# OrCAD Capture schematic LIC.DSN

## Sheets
1 Jogo Roleta Serie: size A; title: Jogo da Roleta Serie
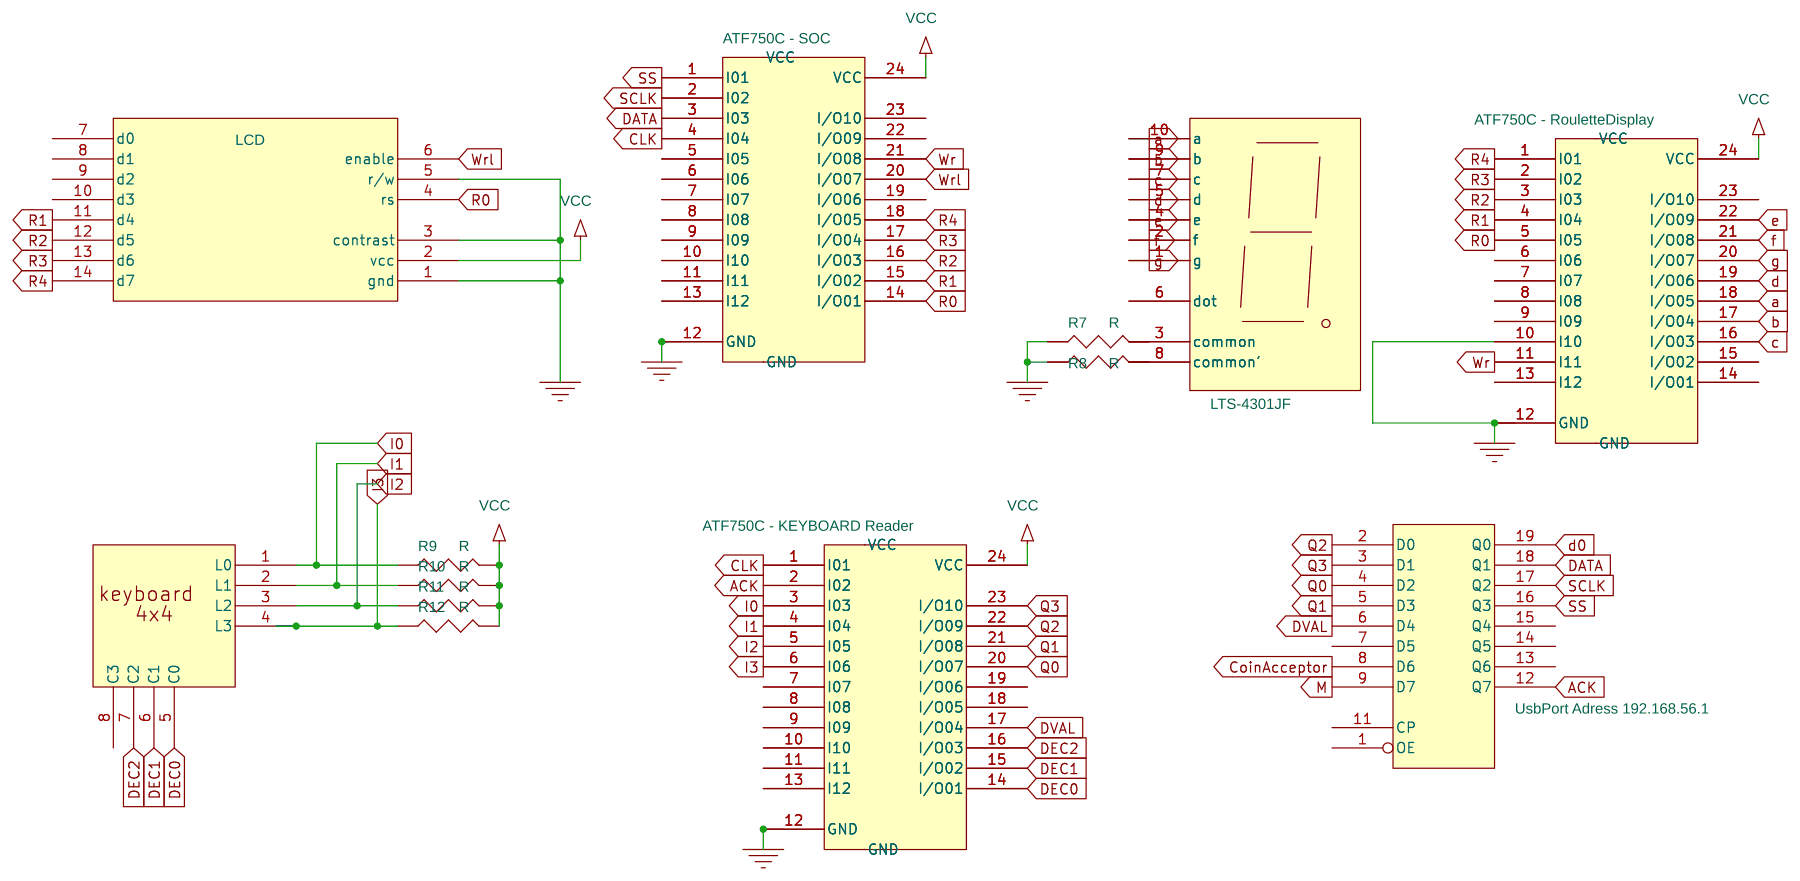
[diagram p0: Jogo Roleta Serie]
2 Jogo Roleta Paralelo: size A; title: Jogo da Roleta Paralelo
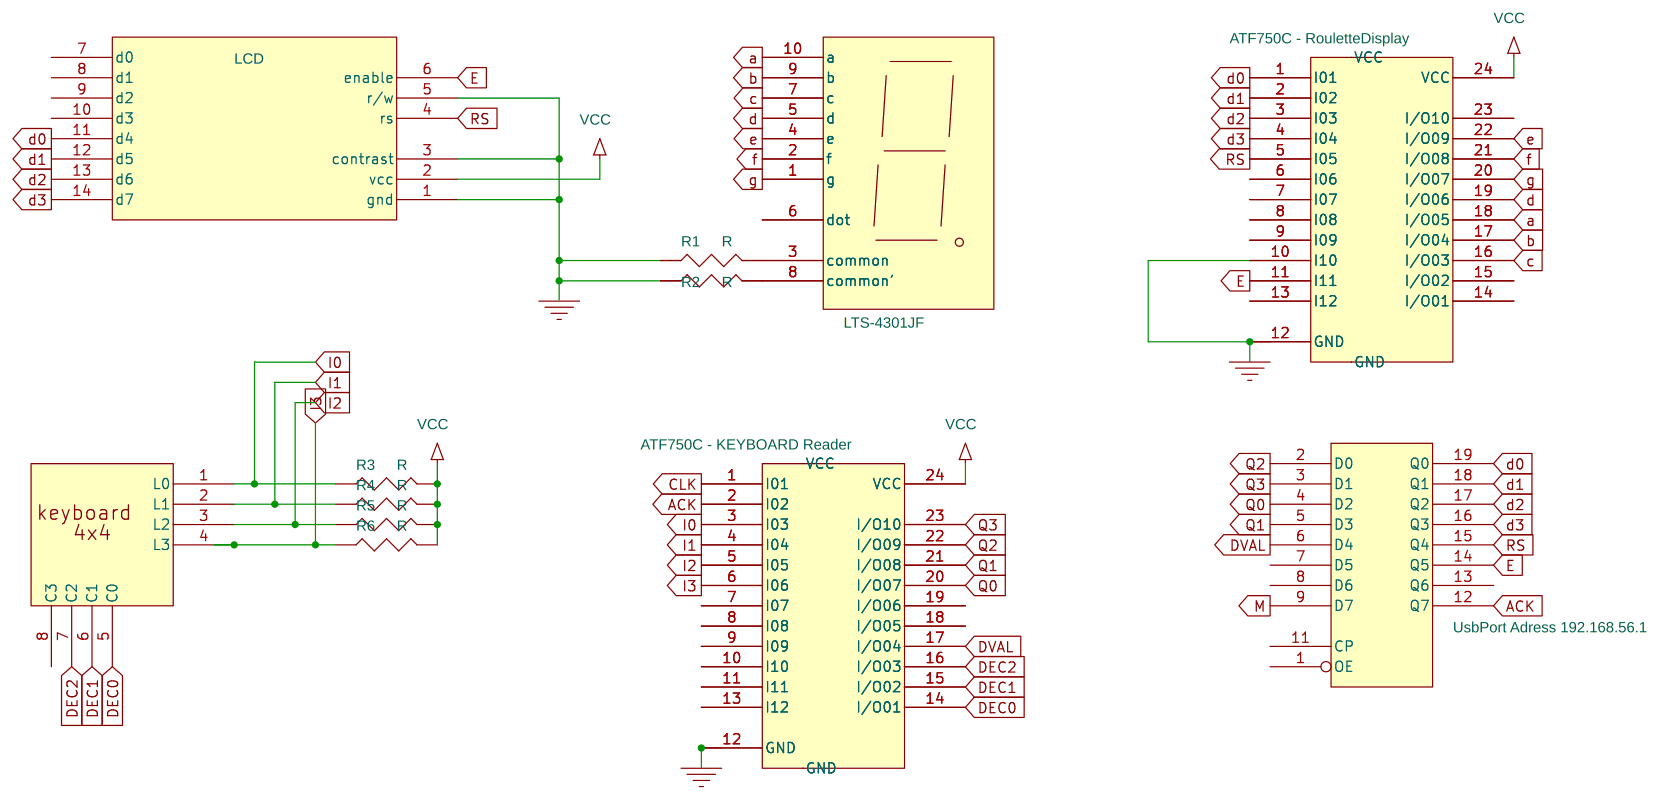
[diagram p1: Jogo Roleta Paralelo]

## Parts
sheet Jogo Roleta Paralelo
R1  R
R2  R
R3  R
R4  R
R5  R
R6  R
U2  LTS-4301JF
U4  LCD
U5  ATF750C - KEYBOARD Reader
U6  4x4
U7  UsbPort Adress 192.168.56.1
U8  ATF750C - RouletteDisplay
sheet Jogo Roleta Serie
R7  R
R8  R
R9  R
R10  R
R11  R
R12  R
U9  ATF750C - RouletteDisplay
U10  LTS-4301JF
U11  LCD
U12  ATF750C - KEYBOARD Reader
U13  4x4
U14  UsbPort Adress 192.168.56.1
U15  ATF750C - SOC

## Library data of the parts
R1-R12 = R
U2 U10 = LTS-4301JF
U4 U11 = LCD_2_16
U5 U12 = ATF750C_1
U6 U13 = 4x4Keyboard
U7 U14 = 74574
U8 U15 = ATF750C
U9 = ATF750C_2

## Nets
GND: R1.1 R2.1 R7.1 R8.1 U4.1(gnd) U4.3(contrast) U4.5(r/w) U5.12(GND) U5.GND U8.10(I10) U8.12(GND) U8.GND U9.10(I10) U9.12(GND) U9.GND U11.1(gnd) U11.3(contrast) U11.5(r/w) U12.12(GND) U12.GND U15.12(GND) U15.GND
VCC: R3.2 R4.2 R5.2 R6.2 R9.2 R10.2 R11.2 R12.2 U4.2(vcc) U5.24(VCC) U5.VCC U8.24(VCC) U8.VCC U9.24(VCC) U9.VCC U11.2(vcc) U12.24(VCC) U12.VCC U15.24(VCC) U15.VCC
a: U2.10(a) U8.18(I/O05) U9.18(I/O05) U10.10(a)
ACK: U5.2(I02) U7.12(Q7) U12.2(I02) U14.12(Q7)
b: U2.9(b) U8.17(I/O04) U9.17(I/O04) U10.9(b)
c: U2.7(c) U8.16(I/O03) U9.16(I/O03) U10.7(c)
CLK: U5.1(I01) U12.1(I01) U15.4(I04)
CoinAcceptor: U14.8(D6)
d: U2.5(d) U8.19(I/O06) U9.19(I/O06) U10.5(d)
d0: U4.11(d4) U7.19(Q0) U8.1(I01) U14.19(Q0)
d1: U4.12(d5) U7.18(Q1) U8.2(I02)
d2: U4.13(d6) U7.17(Q2) U8.3(I03)
d3: U4.14(d7) U7.16(Q3) U8.4(I04)
DATA: U14.18(Q1) U15.3(I03)
DEC0: U5.14(I/O01) U6.5(C0) U12.14(I/O01) U13.5(C0)
DEC1: U5.15(I/O02) U6.6(C1) U12.15(I/O02) U13.6(C1)
DEC2: U5.16(I/O03) U6.7(C2) U12.16(I/O03) U13.7(C2)
DVAL: U5.17(I/O04) U7.6(D4) U12.17(I/O04) U14.6(D4)
E: U2.4(e) U4.6(enable) U7.14(Q5) U8.11(I11) U8.22(I/O09) U9.22(I/O09) U10.4(e)
f: U2.2(f) U8.21(I/O08) U9.21(I/O08) U10.2(f)
g: U2.1(g) U8.20(I/O07) U9.20(I/O07) U10.1(g)
I0: R3.1 R9.1 U5.3(I03) U6.1(L0) U12.3(I03) U13.1(L0)
I1: R4.1 R10.1 U5.4(I04) U6.2(L1) U12.4(I04) U13.2(L1)
I2: R5.1 R11.1 U5.5(I05) U6.3(L2) U12.5(I05) U13.3(L2)
I3: R6.1 R12.1 U5.6(I06) U6.4(L3) U12.6(I06) U13.4(L3)
M: U7.9(D7) U14.9(D7)
Q0: U5.20(I/O07) U7.4(D2) U12.20(I/O07) U14.4(D2)
Q1: U5.21(I/O08) U7.5(D3) U12.21(I/O08) U14.5(D3)
Q2: U5.22(I/O09) U7.2(D0) U12.22(I/O09) U14.2(D0)
Q3: U5.23(I/O10) U7.3(D1) U12.23(I/O10) U14.3(D1)
R0: U9.5(I05) U11.4(rs) U15.14(I/O01)
R1: U9.4(I04) U11.11(d4) U15.15(I/O02)
R2: U9.3(I03) U11.12(d5) U15.16(I/O03)
R3: U9.2(I02) U11.13(d6) U15.17(I/O04)
R4: U9.1(I01) U11.14(d7) U15.18(I/O05)
RS: U4.4(rs) U7.15(Q4) U8.5(I05)
SCLK: U14.17(Q2) U15.2(I02)
SS: U14.16(Q3) U15.1(I01)
Wr: U9.11(I11) U15.21(I/O08)
Wrl: U11.6(enable) U15.20(I/O07)
N12548: R2.2 U2.8(common')
N12552: R1.2 U2.3(common)
N18515: R7.2 U10.3(common)
N18517: R8.2 U10.8(common')

Not connected (* = marked no-connect by the designer): U2 6(dot); U4 7(d0) 8(d1) 9(d2) 10(d3); U5 7(I07) 8(I08) 9(I09) 10(I10) 11(I11) 13(I12) 18(I/O05) 19(I/O06); U6 8(C3); U7 1(OE) 7(D5) 8(D6) 11(CP) 13(Q6); U8 6(I06) 7(I07) 8(I08) 9(I09) 13(I12) 14(I/O01) 15(I/O02) 23(I/O10); U9 6(I06) 7(I07) 8(I08) 9(I09) 13(I12) 14(I/O01) 15(I/O02) 23(I/O10); U10 6(dot); U11 7(d0) 8(d1) 9(d2) 10(d3); U12 7(I07) 8(I08) 9(I09) 10(I10) 11(I11) 13(I12) 18(I/O05) 19(I/O06); U13 8(C3); U14 1(OE) 7(D5) 11(CP) 13(Q6) 14(Q5) 15(Q4); U15 5(I05) 6(I06) 7(I07) 8(I08) 9(I09) 10(I10) 11(I11) 13(I12) 19(I/O06) 22(I/O09) 23(I/O10)
